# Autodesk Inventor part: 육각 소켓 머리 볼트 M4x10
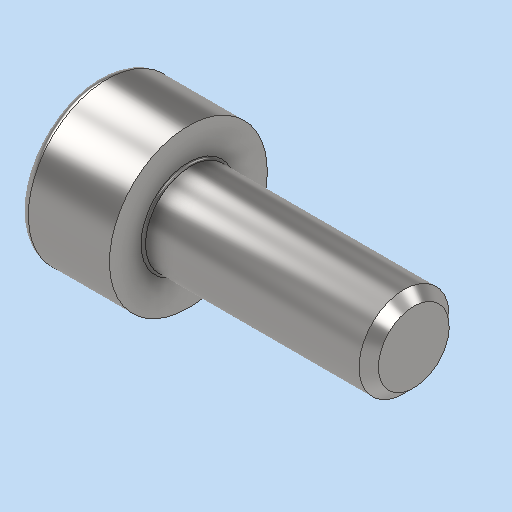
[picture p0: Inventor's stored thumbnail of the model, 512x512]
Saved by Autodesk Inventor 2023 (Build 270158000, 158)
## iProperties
Created: 2024-11
Part Number: 육각 소켓 머리 볼트 M4x10
Material: 강철, 연강
Description: 6각머리 태핑 나사
Document SubType Name: Modeling
Designer: asung
Density: 7.85 g/cm^3
Appearance: 기본값
Author: jhkim
Sending System: Autodesk Inventor 2025
Preprocessor: ST-DEVELOPER v20
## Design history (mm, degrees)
node "육각 소켓 머리 볼트 M4x101"
node "솔리드1"
body "Solid1"
